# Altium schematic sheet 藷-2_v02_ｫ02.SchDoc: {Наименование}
size 420 x 297 mm; DrawnBy: Булычев; Engineer: {Инженер}; DocumentNumber: СИЭТ 21.02.110.000 Э3; SheetNumber: 2; SheetTotal: 6; Title1str: Плата Управления; PageSetup: Record=PageOptions|CenterHorizontal=False|CenterVertical=False|PrintScale=0.95|XCorrection=1.00|YCorrection=1.00|PrintKind=2|BorderSize=5000000|LeftOffset=300|BottomOffset=0|Orientation=2|PaperLength=4200|PaperWidth=2970|Scale=100|PaperSource=15|PrintQuality=-1|MediaType=1|DitherType=10|PaperKind=ISO A3|PrintScaleMode=1; Title2str: (ПУ-2); EngineerName: {Инженер}; DocumentType: Схема электрическая принципиальная; DocumentType1str: {Документ}; DocumentType2str: {Документ}
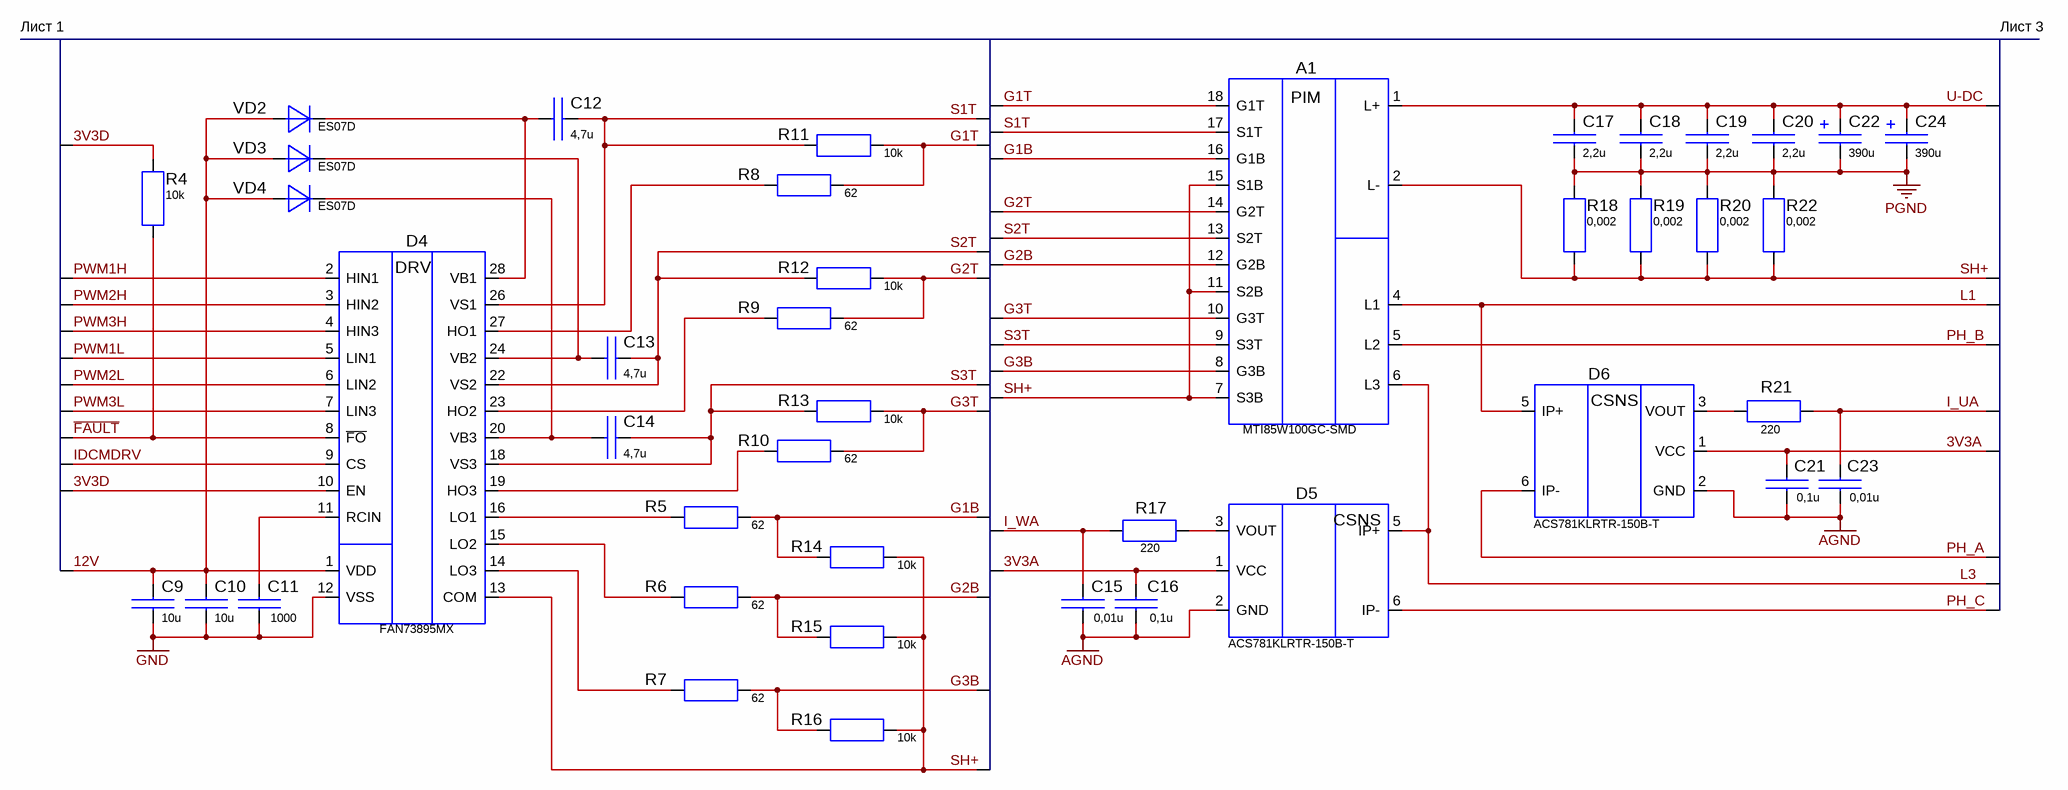
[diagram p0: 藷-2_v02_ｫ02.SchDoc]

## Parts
A1  MTI85W100GC-SMD  [ISOPLUS-DIL]
C9  value 10u  [1206]  (hidden comment: CL31A106KAHNNNE)
C10  value 10u  [1206]  (hidden comment: CL31A106KAHNNNE)
C11  value 1000  [0603]  (hidden comment: CL10C102JB8NNNC)
C12  value 4,7u  [0805]  (hidden comment: CL21A475KAQ)
C13  value 4,7u  [0805]  (hidden comment: CL21A475KAQ)
C14  value 4,7u  [0805]  (hidden comment: CL21A475KAQ)
C15  value 0,01u  [0603]  (hidden comment: CL10B103KB8NNNC)
C16  value 0,1u  [0603]  (hidden comment: CL10B104KB8NNNC)
C17  value 2,2u  [1210]  (hidden comment: CL32B225KCJSNNE)
C18  value 2,2u  [1210]  (hidden comment: CL32B225KCJSNNE)
C19  value 2,2u  [1210]  (hidden comment: CL32B225KCJSNNE)
C20  value 2,2u  [1210]  (hidden comment: CL32B225KCJSNNE)
C21  value 0,1u  [0603]  (hidden comment: CL10B104KB8NNNC)
C22  value 390u  [12.5x35s]  (hidden comment: EKZN101ELL391MK35S)
C23  value 0,01u  [0603]  (hidden comment: CL10B103KB8NNNC)
C24  value 390u  [12.5x35s]  (hidden comment: EKZN101ELL391MK35S)
D4  FAN73895MX  [SOIC-28]
D5  ACS781KLRTR-150B-T  [LR 7-pin PSOF]
D6  ACS781KLRTR-150B-T  [LR 7-pin PSOF]
R4  value 10k  [RC0603]  (hidden comment: RC0603FR-0710KL)
R5  value 62  [RC0603]  (hidden comment: RC0603FR-0762RL)
R6  value 62  [RC0603]  (hidden comment: RC0603FR-0762RL)
R7  value 62  [RC0603]  (hidden comment: RC0603FR-0762RL)
R8  value 62  [RC0603]  (hidden comment: RC0603FR-0762RL)
R9  value 62  [RC0603]  (hidden comment: RC0603FR-0762RL)
R10  value 62  [RC0603]  (hidden comment: RC0603FR-0762RL)
R11  value 10k  [RC0603]  (hidden comment: RC0603FR-0710KL)
R12  value 10k  [RC0603]  (hidden comment: RC0603FR-0710KL)
R13  value 10k  [RC0603]  (hidden comment: RC0603FR-0710KL)
R14  value 10k  [RC0603]  (hidden comment: RC0603FR-0710KL)
R15  value 10k  [RC0603]  (hidden comment: RC0603FR-0710KL)
R16  value 10k  [RC0603]  (hidden comment: RC0603FR-0710KL)
R17  value 220  [RC0603]  (hidden comment: RC0603FR-07220RL)
R18  value 0,002  [CRE2512]  (hidden comment: CRE2512-FZ-R002E-3)
R19  value 0,002  [CRE2512]  (hidden comment: CRE2512-FZ-R002E-3)
R20  value 0,002  [CRE2512]  (hidden comment: CRE2512-FZ-R002E-3)
R21  value 220  [RC0603]  (hidden comment: RC0603FR-07220RL)
R22  value 0,002  [CRE2512]  (hidden comment: CRE2512-FZ-R002E-3)
VD2  ES07D  [DO-219AB(SMF)]
VD3  ES07D  [DO-219AB(SMF)]
VD4  ES07D  [DO-219AB(SMF)]

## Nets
AGND: C15.1 C16.1 C21.1 C23.1 D5.2(GND) D6.2(GND)
GND: C9.1 C10.1 C11.1 D4.12(VSS)
PGND: C17.1 C18.1 C19.1 C20.1 C22.2 C24.2 R18.2 R19.2 R20.2 R22.2
3V3A: C16.2 C21.2 D5.1(VCC) D6.1(VCC)
3V3D: D4.10(EN) R4.1
12V: C9.2 C10.2 D4.1(VDD) VD2.2(A) VD3.2(A) VD4.2(A)
~{FAULT}: D4.8(~{FO}) R4.2
G1B: A1.16(G1B) R5.1 R14.1
G1T: A1.18(G1T) R8.1 R11.2
G2B: A1.12(G2B) R6.1 R15.1
G2T: A1.14(G2T) R9.1 R12.2
G3B: A1.8(G3B) R7.1 R16.1
G3T: A1.10(G3T) R10.1 R13.2
I_UA: C23.2 R21.1
I_WA: C15.2 R17.1
IDCMDRV: D4.9(CS)
L1: A1.4(L1) D6.5(IP+)
L3: A1.6(L3) D5.5(IP+)
PH_A: D6.6(IP-)
PH_B: A1.5(L2)
PH_C: D5.6(IP-)
PWM1H: D4.2(HIN1)
PWM1L: D4.5(LIN1)
PWM2H: D4.3(HIN2)
PWM2L: D4.6(LIN2)
PWM3H: D4.4(HIN3)
PWM3L: D4.7(LIN3)
S1T: A1.17(S1T) C12.1 D4.26(VS1) R11.1
S2T: A1.13(S2T) C13.1 D4.22(VS2) R12.1
S3T: A1.9(S3T) C14.1 D4.18(VS3) R13.1
SH+: A1.2(L-) A1.7(S3B) A1.11(S2B) A1.15(S1B) D4.13(COM) R14.2 R15.2 R16.2 R18.1 R19.1 R20.1 R22.1
U-DC: A1.1(L+) C17.2 C18.2 C19.2 C20.2 C22.1 C24.1
NetC11_2: C11.2 D4.11(RCIN)
NetC12_2: C12.2 D4.28(VB1) VD2.1(C)
NetC13_2: C13.2 D4.24(VB2) VD3.1(C)
NetC14_2: C14.2 D4.20(VB3) VD4.1(C)
NetD4_14: D4.14(LO3) R7.2
NetD4_15: D4.15(LO2) R6.2
NetD4_16: D4.16(LO1) R5.2
NetD4_19: D4.19(HO3) R10.2
NetD4_23: D4.23(HO2) R9.2
NetD4_27: D4.27(HO1) R8.2
NetD5_3: D5.3(VOUT) R17.2
NetD6_3: D6.3(VOUT) R21.2

Not connected (* = marked no-connect by the designer): D4 17(NC) 21(NC) 25(NC); D5 4(NC) 7(NC); D6 4(NC) 7(NC)

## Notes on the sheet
- Лист 1
- Лист 3

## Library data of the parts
A1 = MTI85W100GC-SMD: IGBT-modules; Pdf: MTI85W100GC.pdf; Корпус: ISOPLUS-DIL®
C9 C10 = CL31A106KAHNNNE: 1206, 25V, 10uF; Pdf: GeneralCapacitors_12022.pdf; Voltage: 25 В; Tolerance: ±10%; ТКЕ: X5R
C11 = CL10B103KB8NNNC: 0603 - 50V - 0,01uF; Pdf: GeneralCapacitors_12022.pdf; Voltage: 50В; Type: CL10; Tolerance: ±5%; ТКЕ: NP0
C12-C14 = CL21A475KAQ: 0805, 25V, 4.7uF; Pdf: GeneralCapacitors_12022.pdf; Voltage: 25 В; Type: CL21; Tolerance: ±10%; ТКЕ: X5R; КД: CL21A475KAQNNNG
C15 C23 = CL10B103KB8NNNC: 0603 - 50V - 0,01uF; Pdf: GeneralCapacitors_12022.pdf; Voltage: 50В; Type: CL10; Tolerance: ±10%; ТКЕ: X7R
C16 C21 = CL10B104KB8NNNC: 0603 - 50V - 0,1uF; Pdf: GeneralCapacitors_12022.pdf; Voltage: 50В; Type: CL10; Tolerance: ±10%; ТКЕ: X7R
C17-C20 = CL32B106KBJNNNE: 1210 - 100V - 2,2uF; Pdf: HighCapacitanceCapacitors_12022.pdf; Voltage: 100В; Type: CL32; Tolerance: ±10%; ТКЕ: X7R
C22 C24 = EKZN101ELL391MK35S: 12.5x35 100V 390uF Low impedance Aluminum Capacitor; Tolerance: ±20%; Корпус: 12,5x35; Type: KZN; КД: Электролит. конд. 390мкФ 100В ±20% (EKZN101ELL391MK35S); Замена 1: EKYB101ELL391MK35S; Замена 2: 100ZLJ330M12.5X35 (Rubycon); Замена 3: UHW2A391MHD (Nichicon); Замена 4: 100ZLH330MEFC12.5X35 (Rubycon)
D4 = FAN73895MX: 3-Phase Half-Bridge Gate-Drive IC; Pdf: FAN73895MX.pdf; Корпус: SO14N
D5 D6 = ACS781KLRTR-150B-T: High-Precision Current Sensor IC; Pdf: ACS781-Datasheet.pdf; Type: ACS781
R4-R17 R21 = RC0603: 0603, 0.1W, Thick Film Chip Resistors; Power: 0,1 Вт; Tolerance: ±1%; Pdf: RC0603.pdf; Корпус: 0603; ТКС: ±100 ppm/K
R18-R20 R22 = CRE2512: Resistor, Bourns; Power: 3W; Tolerance: ±1%; Pdf: CRE.pdf; ТКС: ±75 PPM/°C
VD2-VD4 = ES07D: Ultrafast Rectifier; Pdf: es07b.pdf; КД: ES07D-GS08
